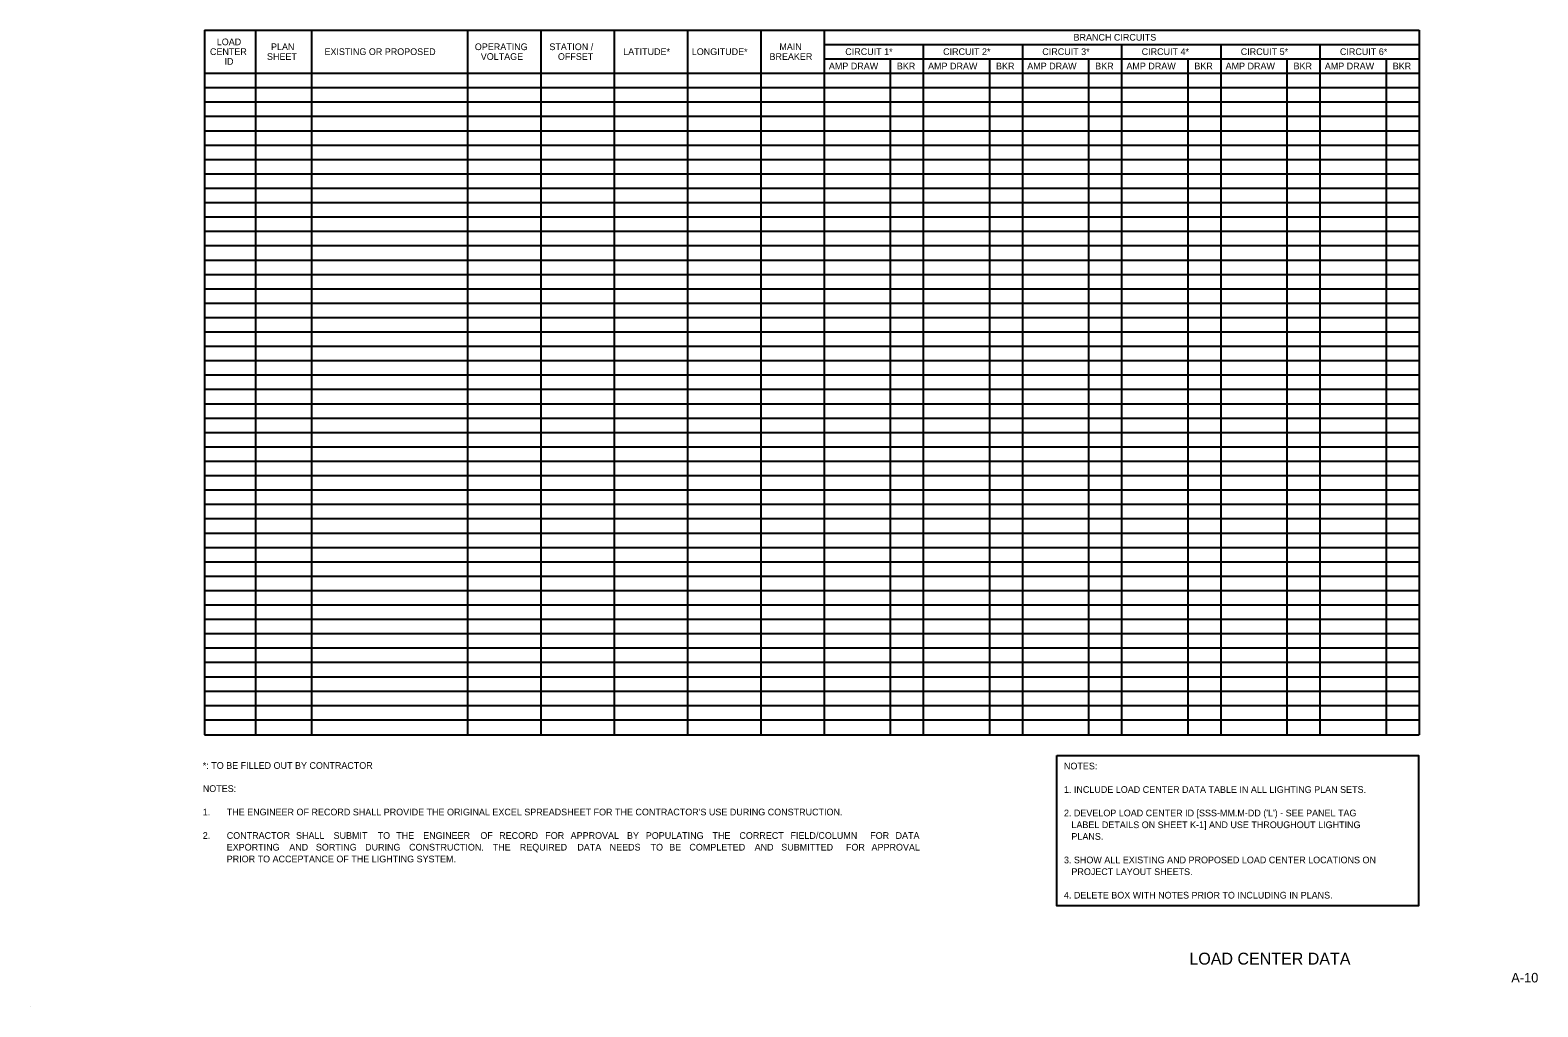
# Model space of a CAD drawing. Extents: x -830028.7 to -830013, y 1290283.4 to 1290293.6.
import ezdxf

# ---------------------------------------------------------------- set-up
doc = ezdxf.new("R2010")
doc.units = 0
for name, color, linetype in [('AdhocPoint_dp', 7, 'Continuous'), ('SumBoxBorder_dp', 7, 'Continuous'), ('SumBoxLines_dp', 7, 'Continuous'), ('TextLabel', 7, 'Continuous'), ('TextMisc', 7, 'Continuous'), ('TextNotes', 7, 'Continuous'), ('TextShtNo', 7, 'Continuous')]:
    doc.layers.add(name, color=color, linetype=linetype)

msp = doc.modelspace()

# ---------------------------------------------------------------- linework, layer by layer
at = {"layer": 'AdhocPoint_dp'}
msp.add_line((-830028.694, 1290283.415), (-830028.694, 1290283.415), dxfattribs=at)
at = {"layer": 'SumBoxBorder_dp'}
for p, q in [((-830026.873, 1290293.612), (-830014.198, 1290293.612)), ((-830026.873, 1290293.612), (-830026.873, 1290286.254)), ((-830020.408, 1290293.462), (-830014.198, 1290293.462)), ((-830020.408, 1290293.462), (-830014.198, 1290293.462)), ((-830014.198, 1290293.612), (-830014.198, 1290286.254)), ((-830020.408, 1290293.312), (-830014.198, 1290293.312)), ((-830020.408, 1290293.312), (-830014.198, 1290293.312)), ((-830026.873, 1290293.162), (-830014.198, 1290293.162)), ((-830026.873, 1290293.162), (-830014.198, 1290293.162)), ((-830026.873, 1290286.254), (-830014.198, 1290286.254))]:
    msp.add_line(p, q, dxfattribs=at)
at = {"layer": 'SumBoxLines_dp'}
for p, q in [((-830026.341, 1290293.612), (-830026.341, 1290286.254)), ((-830026.341, 1290293.612), (-830026.341, 1290286.254)), ((-830025.756, 1290293.612), (-830025.756, 1290286.254)), ((-830025.756, 1290293.612), (-830025.756, 1290286.254)), ((-830024.128, 1290293.612), (-830024.128, 1290286.254)), ((-830024.128, 1290293.612), (-830024.128, 1290286.254)), ((-830023.363, 1290293.612), (-830023.363, 1290286.254)), ((-830023.363, 1290293.612), (-830023.363, 1290286.254)), ((-830022.598, 1290293.612), (-830022.598, 1290286.254)), ((-830022.598, 1290293.612), (-830022.598, 1290286.254)), ((-830021.833, 1290293.612), (-830021.833, 1290286.254)), ((-830021.833, 1290293.612), (-830021.833, 1290286.254)), ((-830021.068, 1290293.612), (-830021.068, 1290286.254)), ((-830021.068, 1290293.612), (-830021.068, 1290286.254)), ((-830020.408, 1290293.612), (-830020.408, 1290286.254)), ((-830020.408, 1290293.612), (-830020.408, 1290286.254)), ((-830019.373, 1290293.462), (-830019.373, 1290286.254)), ((-830019.373, 1290293.462), (-830019.373, 1290286.254)), ((-830018.338, 1290293.462), (-830018.338, 1290286.254)), ((-830018.338, 1290293.462), (-830018.338, 1290286.254)), ((-830017.303, 1290293.462), (-830017.303, 1290286.254)), ((-830017.303, 1290293.462), (-830017.303, 1290286.254)), ((-830016.268, 1290293.462), (-830016.268, 1290286.254)), ((-830016.268, 1290293.462), (-830016.268, 1290286.254)), ((-830015.233, 1290293.462), (-830015.233, 1290286.254)), ((-830015.233, 1290293.462), (-830015.233, 1290286.254)), ((-830019.718, 1290293.312), (-830019.718, 1290286.254)), ((-830019.718, 1290293.312), (-830019.718, 1290286.254)), ((-830018.683, 1290293.312), (-830018.683, 1290286.254)), ((-830018.683, 1290293.312), (-830018.683, 1290286.254)), ((-830017.648, 1290293.312), (-830017.648, 1290286.254)), ((-830017.648, 1290293.312), (-830017.648, 1290286.254)), ((-830016.613, 1290293.312), (-830016.613, 1290286.254)), ((-830016.613, 1290293.312), (-830016.613, 1290286.254)), ((-830015.578, 1290293.312), (-830015.578, 1290286.254)), ((-830015.578, 1290293.312), (-830015.578, 1290286.254)), ((-830014.543, 1290293.312), (-830014.543, 1290286.254)), ((-830014.543, 1290293.312), (-830014.543, 1290286.254)), ((-830026.873, 1290293.012), (-830014.198, 1290293.012)), ((-830025.756, 1290293.012), (-830014.198, 1290293.012)), ((-830026.873, 1290292.862), (-830014.198, 1290292.862)), ((-830026.873, 1290292.862), (-830014.198, 1290292.862)), ((-830026.873, 1290292.712), (-830014.198, 1290292.712)), ((-830026.873, 1290292.712), (-830014.198, 1290292.712)), ((-830026.873, 1290292.562), (-830014.198, 1290292.562)), ((-830026.873, 1290292.562), (-830014.198, 1290292.562)), ((-830026.873, 1290292.412), (-830014.198, 1290292.412)), ((-830026.873, 1290292.412), (-830014.198, 1290292.412)), ((-830026.873, 1290292.262), (-830014.198, 1290292.262)), ((-830026.873, 1290292.262), (-830014.198, 1290292.262)), ((-830026.873, 1290292.112), (-830014.198, 1290292.112)), ((-830026.873, 1290292.112), (-830014.198, 1290292.112)), ((-830026.873, 1290291.962), (-830014.198, 1290291.962)), ((-830026.873, 1290291.962), (-830014.198, 1290291.962)), ((-830026.873, 1290291.812), (-830014.198, 1290291.812)), ((-830026.873, 1290291.812), (-830014.198, 1290291.812)), ((-830026.873, 1290291.662), (-830014.198, 1290291.662)), ((-830026.873, 1290291.662), (-830014.198, 1290291.662)), ((-830026.873, 1290291.512), (-830014.198, 1290291.512)), ((-830026.873, 1290291.512), (-830014.198, 1290291.512)), ((-830026.873, 1290291.362), (-830014.198, 1290291.362)), ((-830026.873, 1290291.362), (-830014.198, 1290291.362)), ((-830026.873, 1290291.212), (-830014.198, 1290291.212)), ((-830026.873, 1290291.212), (-830014.198, 1290291.212)), ((-830026.873, 1290291.062), (-830014.198, 1290291.062)), ((-830026.873, 1290291.062), (-830014.198, 1290291.062)), ((-830026.873, 1290290.912), (-830014.198, 1290290.912)), ((-830026.873, 1290290.912), (-830014.198, 1290290.912)), ((-830026.873, 1290290.762), (-830014.198, 1290290.762)), ((-830026.873, 1290290.762), (-830014.198, 1290290.762)), ((-830026.873, 1290290.612), (-830014.198, 1290290.612)), ((-830026.873, 1290290.612), (-830014.198, 1290290.612)), ((-830026.873, 1290290.462), (-830014.198, 1290290.462)), ((-830026.873, 1290290.462), (-830014.198, 1290290.462)), ((-830026.873, 1290290.312), (-830014.198, 1290290.312)), ((-830026.873, 1290290.312), (-830014.198, 1290290.312)), ((-830026.873, 1290290.162), (-830014.198, 1290290.162)), ((-830026.873, 1290290.162), (-830014.198, 1290290.162)), ((-830026.873, 1290290.012), (-830014.198, 1290290.012)), ((-830026.873, 1290290.012), (-830014.198, 1290290.012)), ((-830026.873, 1290289.862), (-830014.198, 1290289.862)), ((-830026.873, 1290289.862), (-830014.198, 1290289.862)), ((-830026.873, 1290289.712), (-830014.198, 1290289.712)), ((-830026.873, 1290289.712), (-830014.198, 1290289.712)), ((-830026.873, 1290289.562), (-830014.198, 1290289.562)), ((-830026.873, 1290289.562), (-830014.198, 1290289.562)), ((-830026.873, 1290289.412), (-830014.198, 1290289.412)), ((-830026.873, 1290289.412), (-830014.198, 1290289.412)), ((-830026.873, 1290289.262), (-830014.198, 1290289.262)), ((-830026.873, 1290289.262), (-830014.198, 1290289.262)), ((-830026.873, 1290289.112), (-830014.198, 1290289.112)), ((-830026.873, 1290289.112), (-830014.198, 1290289.112)), ((-830026.873, 1290288.962), (-830014.198, 1290288.962)), ((-830026.873, 1290288.962), (-830014.198, 1290288.962)), ((-830026.873, 1290288.812), (-830014.198, 1290288.812)), ((-830026.873, 1290288.812), (-830014.198, 1290288.812)), ((-830026.873, 1290288.662), (-830014.198, 1290288.662)), ((-830026.873, 1290288.662), (-830014.198, 1290288.662)), ((-830026.873, 1290288.512), (-830014.198, 1290288.512)), ((-830026.873, 1290288.512), (-830014.198, 1290288.512)), ((-830026.873, 1290288.362), (-830014.198, 1290288.362)), ((-830026.873, 1290288.362), (-830014.198, 1290288.362)), ((-830026.873, 1290288.212), (-830014.198, 1290288.212)), ((-830026.873, 1290288.212), (-830014.198, 1290288.212)), ((-830026.873, 1290288.062), (-830014.198, 1290288.062)), ((-830026.873, 1290288.062), (-830014.198, 1290288.062)), ((-830026.873, 1290287.912), (-830014.198, 1290287.912)), ((-830026.873, 1290287.912), (-830014.198, 1290287.912)), ((-830026.873, 1290287.762), (-830014.198, 1290287.762)), ((-830026.873, 1290287.762), (-830014.198, 1290287.762)), ((-830026.873, 1290287.612), (-830014.198, 1290287.612)), ((-830026.873, 1290287.612), (-830014.198, 1290287.612)), ((-830026.873, 1290287.462), (-830014.198, 1290287.462)), ((-830026.873, 1290287.462), (-830014.198, 1290287.462)), ((-830026.873, 1290287.312), (-830014.198, 1290287.312)), ((-830026.873, 1290287.312), (-830014.198, 1290287.312)), ((-830026.873, 1290287.162), (-830014.198, 1290287.162)), ((-830026.873, 1290287.162), (-830014.198, 1290287.162)), ((-830026.873, 1290287.012), (-830014.198, 1290287.012)), ((-830026.873, 1290287.012), (-830014.198, 1290287.012)), ((-830026.873, 1290286.862), (-830014.198, 1290286.862)), ((-830026.873, 1290286.862), (-830014.198, 1290286.862)), ((-830026.873, 1290286.712), (-830014.198, 1290286.712)), ((-830026.873, 1290286.712), (-830014.198, 1290286.712)), ((-830026.873, 1290286.562), (-830014.198, 1290286.562)), ((-830026.873, 1290286.562), (-830014.198, 1290286.562)), ((-830026.873, 1290286.412), (-830014.198, 1290286.412)), ((-830026.873, 1290286.412), (-830014.198, 1290286.412))]:
    msp.add_line(p, q, dxfattribs=at)
at = {"layer": 'TextNotes'}
msp.add_lwpolyline([(-830017.978, 1290286.04), (-830014.204, 1290286.04), (-830014.204, 1290284.47), (-830017.978, 1290284.47)], close=True, dxfattribs=at)

# ---------------------------------------------------------------- texts
at = {"layer": 'TextLabel'}
for s, p in [('LOAD', (-830026.746, 1290293.454)), ('PLAN', (-830026.18, 1290293.403)), ('OPERATING', (-830024.053, 1290293.403)), ('STATION /', (-830023.275, 1290293.403)), ('MAIN', (-830020.875, 1290293.403)), ('BRANCH CIRCUITS', (-830017.805, 1290293.502)), ('CENTER', (-830026.817, 1290293.352)), ('ID', (-830026.665, 1290293.25)), ('SHEET', (-830026.222, 1290293.301)), ('EXISTING OR PROPOSED', (-830025.622, 1290293.352)), ('VOLTAGE', (-830023.991, 1290293.301)), ('OFFSET', (-830023.186, 1290293.301)), ('LATITUDE*', (-830022.505, 1290293.352)), ('LONGITUDE*', (-830021.789, 1290293.352)), ('BREAKER', (-830020.978, 1290293.301)), ('CIRCUIT 1*', (-830020.187, 1290293.352)), ('CIRCUIT 2*', (-830019.166, 1290293.352)), ('CIRCUIT 3*', (-830018.131, 1290293.352)), ('CIRCUIT 4*', (-830017.094, 1290293.352)), ('CIRCUIT 5*', (-830016.06, 1290293.352)), ('CIRCUIT 6*', (-830015.025, 1290293.352)), ('AMP DRAW', (-830020.358, 1290293.202)), ('BKR', (-830019.649, 1290293.202)), ('AMP DRAW', (-830019.323, 1290293.202)), ('BKR', (-830018.614, 1290293.202)), ('AMP DRAW', (-830018.288, 1290293.202)), ('BKR', (-830017.579, 1290293.202)), ('AMP DRAW', (-830017.253, 1290293.202)), ('BKR', (-830016.544, 1290293.202)), ('AMP DRAW', (-830016.218, 1290293.202)), ('BKR', (-830015.509, 1290293.202)), ('AMP DRAW', (-830015.183, 1290293.202)), ('BKR', (-830014.474, 1290293.202))]:
    msp.add_text(s, height=0.07, dxfattribs=at).set_placement(p)
at = {"layer": 'TextMisc'}
msp.add_text('       LOAD CENTER DATA        ', height=0.125, dxfattribs=at).set_placement((-830016.921, 1290283.856))
at = {"layer": 'TextNotes'}
for s, p in [('*: TO BE FILLED OUT BY CONTRACTOR', (-830026.892, 1290285.9)), ('NOTES:', (-830017.905, 1290285.894)), ('NOTES:', (-830026.892, 1290285.659)), ('1. INCLUDE LOAD CENTER DATA TABLE IN ALL LIGHTING PLAN SETS.', (-830017.905, 1290285.649)), ('1.', (-830026.892, 1290285.414)), ("THE ENGINEER OF RECORD SHALL PROVIDE THE ORIGINAL EXCEL SPREADSHEET FOR THE CONTRACTOR'S USE DURING CONSTRUCTION.", (-830026.642, 1290285.414)), ("2. DEVELOP LOAD CENTER ID [SSS-MM.M-DD ('L') - SEE PANEL TAG", (-830017.905, 1290285.404)), ('   LABEL DETAILS ON SHEET K-1] AND USE THROUGHOUT LIGHTING', (-830017.905, 1290285.281)), ('2.', (-830026.892, 1290285.169)), ('CONTRACTOR ', (-830026.642, 1290285.169)), ('SHALL ', (-830025.919, 1290285.169)), ('SUBMIT ', (-830025.527, 1290285.169)), ('TO ', (-830025.067, 1290285.169)), ('THE ', (-830024.873, 1290285.169)), ('ENGINEER ', (-830024.592, 1290285.169)), ('OF ', (-830023.995, 1290285.169)), ('RECORD ', (-830023.799, 1290285.169)), ('FOR ', (-830023.318, 1290285.169)), ('APPROVAL ', (-830023.053, 1290285.169)), ('BY ', (-830022.465, 1290285.169)), ('POPULATING ', (-830022.269, 1290285.169)), ('THE ', (-830021.573, 1290285.169)), ('CORRECT ', (-830021.292, 1290285.169)), ('FIELD/COLUMN ', (-830020.759, 1290285.169)), ('FOR ', (-830019.927, 1290285.169)), ('DATA ', (-830019.662, 1290285.169)), ('   PLANS.', (-830017.905, 1290285.159)), ('EXPORTING ', (-830026.642, 1290285.047)), ('PRIOR TO ACCEPTANCE OF THE LIGHTING SYSTEM. ', (-830026.642, 1290284.924)), ('AND ', (-830025.99, 1290285.047)), ('SORTING ', (-830025.712, 1290285.047)), ('DURING ', (-830025.198, 1290285.047)), ('CONSTRUCTION. ', (-830024.739, 1290285.047)), ('THE ', (-830023.867, 1290285.047)), ('REQUIRED ', (-830023.584, 1290285.047)), ('DATA ', (-830022.983, 1290285.047)), ('NEEDS ', (-830022.646, 1290285.047)), ('TO ', (-830022.219, 1290285.047)), ('BE ', (-830022.024, 1290285.047)), ('COMPLETED ', (-830021.814, 1290285.047)), ('AND ', (-830021.133, 1290285.047)), ('SUBMITTED ', (-830020.855, 1290285.047)), ('FOR ', (-830020.18, 1290285.047)), ('APPROVAL ', (-830019.913, 1290285.047)), ('3. SHOW ALL EXISTING AND PROPOSED LOAD CENTER LOCATIONS ON', (-830017.905, 1290284.914)), ('   PROJECT LAYOUT SHEETS.', (-830017.905, 1290284.791)), ('4. DELETE BOX WITH NOTES PRIOR TO INCLUDING IN PLANS.', (-830017.905, 1290284.546))]:
    msp.add_text(s, height=0.07, dxfattribs=at).set_placement(p)
at = {"layer": 'TextShtNo'}
msp.add_text('A-10', height=0.1, dxfattribs=at).set_placement((-830013.237, 1290283.67))

doc.saveas('drawing.dxf')
